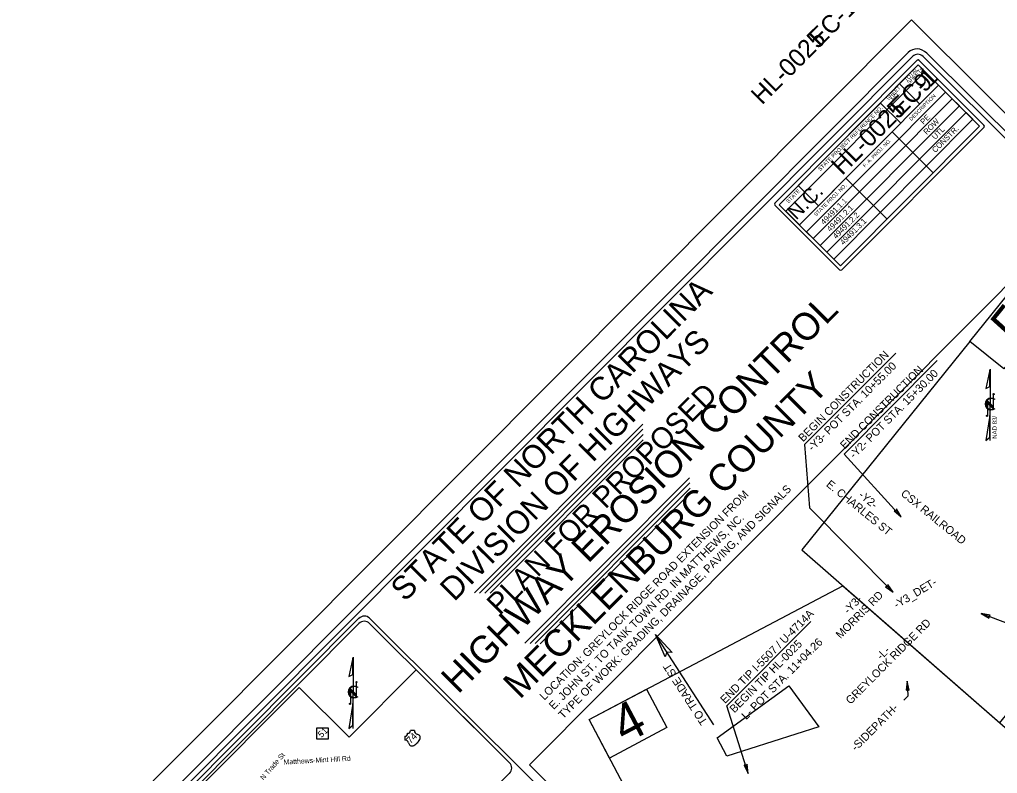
# Model space of a CAD drawing. Extents: x 1484932 to 1495672, y 495497 to 506262.
# Drawn here: x 1484932 to 1488841, y 498393 to 501407 of the extents above; entities that cross this region are included whole.
import ezdxf

# ---------------------------------------------------------------- set-up
doc = ezdxf.new("R2010")
doc.units = 0
for name, color, linetype in [('Default', 7, 'Continuous'), ('Old_Level_18', 7, 'Continuous'), ('Prop Dimension', 7, 'Continuous'), ('Prop DSN Text', 7, 'Continuous'), ('Prop DSN White Annotation Label', 7, 'Continuous'), ('Prop EOT', 7, 'Continuous'), ('Prop Horizontal Alignment Station Label', 7, 'Continuous'), ('Prop Terminator CELL', 7, 'Continuous'), ('Scratch_Level_4', 7, 'Continuous'), ('Sheet Data Field CELL', 7, 'Continuous'), ('Sheet North Arrow CELL', 7, 'Continuous'), ('Sheet Plot Border Outside CELL', 7, 'Continuous')]:
    doc.layers.add(name, color=color, linetype=linetype)

msp = doc.modelspace()

# ---------------------------------------------------------------- linework, layer by layer
at = {"layer": 'Default'}
for p, q in [((1486749.9, 499114.4), (1487422.5, 499789.9)), ((1486770.5, 499113.7), (1487423.4, 499769.3)), ((1486791.2, 499113), (1487425, 499748.6)), ((1486812.6, 499113.1), (1487423.8, 499726.9)), ((1486951.5, 498913.7), (1487610.2, 499575.2)), ((1486972.1, 498913), (1487611.1, 499554.6)), ((1486992.7, 498912.3), (1487611.9, 499534)), ((1487013.3, 498911.5), (1487612.7, 499513.4))]:
    msp.add_line(p, q, dxfattribs=at)
at = {"layer": 'Old_Level_18'}
for p, q in [((1490710.4, 499129.2), (1488558.1, 501272.7)), ((1485457.2, 498202.7), (1488502.1, 501260.3)), ((1488519.3, 501244), (1487950.3, 500672.7)), ((1488786.7, 500985.1), (1488527.5, 501243.8)), ((1488543.4, 501258.8), (1490253, 499556.3)), ((1488523.7, 501225.3), (1487967.5, 500666.8)), ((1487994.9, 500640.3), (1488550.8, 501198.4)), ((1488523.7, 501225.3), (1488449.3, 501149.8)), ((1488550.8, 501198.4), (1488523.7, 501225.3)), ((1488769.3, 500980.7), (1488523.7, 501225.3)), ((1488449.3, 501149.8), (1488529.9, 501068.7)), ((1488605.2, 501144.3), (1488049.3, 500586.1)), ((1488077.2, 500558.3), (1488633.1, 501116.5)), ((1488633.1, 501116.5), (1488605.2, 501144.3)), ((1488043.9, 500743.5), (1488372.9, 501073.1)), ((1488660, 501089.6), (1488103.8, 500531)), ((1488372.9, 501073.1), (1488453.9, 500992.3)), ((1488688.3, 501062.2), (1488660, 501089.6)), ((1488132.1, 500503.7), (1488688.3, 501062.2)), ((1488714.9, 501035.8), (1488158.6, 500477.2)), ((1488742.7, 501008), (1488714.9, 501035.8)), ((1488186.5, 500449.5), (1488742.7, 501008)), ((1488769.4, 500980.7), (1488213.1, 500422.2)), ((1488218.8, 500406.1), (1488787.1, 500976)), ((1488453.9, 500992.3), (1488419.9, 500958.1)), ((1488419.9, 500958.1), (1488584.1, 500794.7)), ((1488235, 500772.6), (1488125.3, 500662.4)), ((1488399.2, 500609), (1488235, 500772.6)), ((1488125.3, 500662.4), (1488043.9, 500743.5)), ((1487950.7, 500664.5), (1488209.7, 500406.5)), ((1487967.5, 500666.8), (1488213.1, 500422.2)), ((1488049.3, 500586.1), (1487994.9, 500640.3)), ((1488103.8, 500531), (1488077.2, 500558.3)), ((1488158.6, 500477.2), (1488132.1, 500503.7)), ((1488213.1, 500422.2), (1488186.5, 500449.5)), ((1485486.3, 498207.8), (1486288.2, 499013)), ((1486331.1, 499013.1), (1487008.3, 498338.6)), ((1485507.1, 498207.8), (1486288.3, 498992.3)), ((1486331.1, 498992.4), (1486890.1, 498435.7))]:
    msp.add_line(p, q, dxfattribs=at)
msp.add_lwpolyline([(1488483.8, 501275.3), (1485308.3, 498086.6)], dxfattribs=at)
for centre, start, end in [((1486309.7, 498991.6), 45.1186, 135.1186), ((1486309.7, 498970.9), 45.1186, 135.1186), ((1486868.7, 498414.2), 315.1186, 45.1186)]:
    msp.add_arc(centre, 30.3, start, end, dxfattribs=at)
for centre, major_axis, ratio, start_param, end_param in [((1488522.4, 501236.9), (-38.6, 38.4), 0.927398, 4.712389, 6.283185), ((1488523.6, 501238.9), (-21.4, 21.3), 0.927398, 4.712389, 6.283185), ((1488523.4, 501238.7), (-4.72, 4.7), 0.927398, 4.712389, 6.283185), ((1488523.5, 501239.8), (-4.29, 4.27), 0.927398, 4.712389, 6.283185), ((1488782.4, 500980.7), (-4.72, 4.7), 0.93232, 3.141593, 4.712389), ((1487954.6, 500668.5), (4.29, -4.27), 0.927398, 3.141593, 4.712389), ((1488214.1, 500410.8), (4.72, -4.7), 0.927398, 4.712389, 6.283185)]:
    msp.add_ellipse(centre, major_axis=major_axis, ratio=ratio, start_param=start_param, end_param=end_param, dxfattribs=at)
at = {"layer": 'Prop Dimension'}
for p, q in [((1488434, 500073.4), (1488069.9, 499707.7)), ((1488600.1, 500043.2), (1488228.3, 499669.8)), ((1488228.3, 499669.8), (1488455.9, 499419.4)), ((1488095, 498999.7), (1487759.2, 498662.6)), ((1489377.9, 498804), (1488775.9, 499031.9)), ((1488479.7, 498761.9), (1488482.6, 498702.3)), ((1488482.6, 498702.3), (1488466.7, 498686.4)), ((1487844.4, 498392.9), (1487759.2, 498662.6))]:
    msp.add_line(p, q, dxfattribs=at)
msp.add_lwpolyline([(1488069.9, 499707.7), (1488089.2, 499455.4), (1488423.2, 499117.7), (1488423.2, 499117.7)], dxfattribs=at)
at = {"layer": 'Prop DSN Text'}
msp.add_line((1487707.1, 498587.7), (1487474, 498947.7), dxfattribs=at)
at = {"layer": 'Prop DSN White Annotation Label'}
for points in [[(1489043.4, 500231.5), (1488865.6, 500011), (1488730.5, 500119.9), (1488908.3, 500340.4)], [(1488865.6, 500011), (1488730.5, 500119.9), (1488058.3, 499286.4), (1488849.5, 498594.9), (1489725.7, 499681.3), (1489043.4, 500231.5)], [(1487208.7, 498608.1), (1488222.1, 499143.2), (1488965.4, 498493.7), (1489025.4, 498380), (1487698.9, 497679.6)], [(1487208.7, 498608.1), (1487438.3, 498729.4), (1487519.4, 498575.9), (1487289.7, 498454.6)]]:
    msp.add_lwpolyline(points, close=True, dxfattribs=at)
at = {"layer": 'Prop EOT'}
for p, q in [((1486471.5, 498541.9), (1486471.5, 498526)), ((1486510.1, 498564.8), (1486494.3, 498564.6))]:
    msp.add_line(p, q, dxfattribs=at)
msp.add_lwpolyline([(1486120.2, 498530.3), (1486120.2, 498575.4), (1486165.2, 498575.5), (1486165.3, 498530.4)], close=True, dxfattribs=at)
for centre, radius, start, end in [((1486472.2, 498552.4), 10.6, 266.1975, 4.6682), ((1486483.7, 498563.9), 10.6, 265.569, 4.108), ((1486524.6, 498563.4), 14.5, 174.6433, 256.9786), ((1486519.8, 498535.5), 13.8, 344.5208, 83.5807), ((1486506, 498540.2), 28.4, 309.2442, 342.8049), ((1486472.8, 498511.5), 14.5, 13.2587, 95.1575), ((1486500.7, 498516.5), 13.8, 186.662, 285.7164), ((1486495.9, 498530.3), 28.4, 287.4324, 321.0045), ((1486521.5, 498510.3), 4.03, 81.6193, 148.6808), ((1486526, 498514.8), 4.03, 121.5524, 186.2514)]:
    msp.add_arc(centre, radius, start, end, dxfattribs=at)
at = {"layer": 'Prop Terminator CELL'}
for points in [[(1488427.6, 499442.4), (1488455.9, 499419.4), (1488436.9, 499450.9), (1488435.1, 499443.2)], [(1488393.5, 499138.9), (1488423.2, 499117.7), (1488402.3, 499147.9), (1488401, 499140.2)], [(1488811.7, 499025), (1488775.9, 499031.9), (1488807.5, 499013.1), (1488805.4, 499020.7)], [(1487511.7, 498859.5), (1487474, 498947.7), (1487539.8, 498877), (1487519.1, 498878)], [(1488487.6, 498726.2), (1488479.7, 498761.9), (1488475.1, 498725.4), (1488481.2, 498730.3)], [(1487827.6, 498425.4), (1487844.4, 498392.9), (1487839.6, 498429.3), (1487834.9, 498423)]]:
    msp.add_lwpolyline(points, close=True, dxfattribs=at)
at = {"layer": 'Scratch_Level_4'}
for p, q in [((1488508.1, 501403.2), (1488508.1, 501403.2)), ((1488541.2, 501351.2), (1488541.2, 501351.2)), ((1486517.2, 498807.1), (1486890.1, 498435.7)), ((1485525.4, 498210.9), (1486049, 498736.6)), ((1486890.2, 498393.4), (1486119.3, 497619.4))]:
    msp.add_line(p, q, dxfattribs=at)
for points in [[(1486969.7, 498427.7), (1489005, 500471.4), (1490008.1, 499472.4), (1487972.8, 497428.7)], [(1487759, 498462.3), (1487720.6, 498534.8), (1488006.4, 498743.3), (1488126.2, 498579.3)]]:
    msp.add_lwpolyline(points, close=True, dxfattribs=at)
msp.add_lwpolyline([(1486049, 498736.6), (1486248.8, 498537.6), (1486517.2, 498807.1)], dxfattribs=at)
msp.add_arc((1486869, 498414.5), 29.9, 315.1181, 45.1181, dxfattribs=at)
at = {"layer": 'Sheet North Arrow CELL'}
for p, q in [((1488812, 499724.1), (1488812.2, 500008.5)), ((1488822.9, 499909.5), (1488822.8, 499851.2)), ((1488822.8, 499860.3), (1488801.1, 499882)), ((1488801.1, 499882), (1488801.1, 499822.7)), ((1488822.8, 499858.1), (1488801.1, 499879.9)), ((1488801.1, 499879.9), (1488801.1, 499874.6)), ((1488822.8, 499852.8), (1488801.1, 499874.6)), ((1488801.1, 499874.6), (1488822.8, 499852.8)), ((1488822.8, 499851.2), (1488801.1, 499872.9)), ((1488830.9, 499887.8), (1488831.2, 499887.6)), ((1488822.8, 499852.8), (1488822.8, 499858.1)), ((1486265.7, 498572.7), (1486266, 498857.2)), ((1486276.6, 498708.9), (1486254.8, 498730.7)), ((1486254.8, 498730.7), (1486254.8, 498671.3)), ((1486276.6, 498706.8), (1486254.8, 498728.5)), ((1486254.8, 498728.5), (1486254.8, 498723.2)), ((1486276.6, 498758.2), (1486276.6, 498699.8)), ((1486284.6, 498736.4), (1486284.9, 498736.2)), ((1486276.6, 498701.4), (1486254.8, 498723.2)), ((1486254.8, 498723.2), (1486276.6, 498701.4)), ((1486276.6, 498699.8), (1486254.8, 498721.6)), ((1486276.6, 498701.4), (1486276.6, 498706.8))]:
    msp.add_line(p, q, dxfattribs=at)
for points in [[(1488810.3, 500006), (1488794, 499932.2), (1488810.2, 499940.4)], [(1488809.8, 499824.3), (1488793.6, 499724.1), (1488809.7, 499736.8)], [(1486264, 498854.7), (1486247.7, 498780.8), (1486263.9, 498789)], [(1486263.5, 498673), (1486247.3, 498572.7), (1486263.4, 498585.4)]]:
    msp.add_lwpolyline(points, close=True, dxfattribs=at)
for centre in [(1488825.2, 499909.5), (1488798.7, 499822.6), (1486278.9, 498758.1), (1486252.5, 498671.3)]:
    msp.add_circle(centre, 2.32, dxfattribs=at)
for centre, radius, start, end in [((1488815.1, 499869.9), 23.9, 47.7961, 312.3501), ((1488817.5, 499869.9), 22.4, 53.0511, 308.5848), ((1486268.9, 498718.5), 23.9, 47.7961, 312.3501), ((1486271.2, 498718.5), 22.4, 53.0511, 308.5848)]:
    msp.add_arc(centre, radius, start, end, dxfattribs=at)
at = {"layer": 'Sheet Plot Border Outside CELL'}
msp.add_lwpolyline([(1488496.6, 501405.6), (1484931.7, 497825.9), (1487270, 495497.3), (1490834.9, 499077)], close=True, dxfattribs=at)

# ---------------------------------------------------------------- texts
at = {"layer": 'Default'}
for s, height, rotation, p in [('EC-1', 71.07, 45.1182, (1488129.5, 501294.2)), ('HL-0025', 71.92, 45.1187, (1487899.5, 501062.7)), ('STATE OF NORTH CAROLINA', 92.714, 45.1186, (1486471.9, 499076.2)), ('HIGHWAY EROSION CONTROL', 109.027, 45.1186, (1486684.4, 498707.4)), ('DIVISION OF HIGHWAYS', 92.714, 45.1186, (1486669.1, 499077)), ('MECKLENBURG COUNTY', 107.571, 45.1182, (1486931.2, 498686)), ('PLAN FOR PROPOSED', 84.79, 45.1186, (1486851, 499022.2)), ('N Trade St', 20, 48.7859, (1485906.4, 498364.8)), ('Matthews-Mint Hill Rd', 20, 3.2578, (1485987.7, 498428.4))]:
    msp.add_text(s, height=height, rotation=rotation, dxfattribs=at).set_placement(p)
at = {"layer": 'Old_Level_18'}
for s, height, rotation, p in [('EC-1', 72.03, 45.1186, (1488453.1, 501015.7)), ('TOTAL', 15.45, 45.1186, (1488477, 501157)), ('SHEETS', 15.45, 45.1186, (1488488.5, 501147.2)), ('9', 71.9, 45.1187, (1488549.1, 501112.2)), ('SHEET', 15.45, 45.1186, (1488405.1, 501082.2)), ('NO.', 15.45, 45.1186, (1488424.9, 501080.7)), ('HL-0025', 72.03, 45.1186, (1488219.7, 500781.4)), ('DESCRIPTION', 14.828, 45.1186, (1488496.4, 501000.7)), ('STATE PROJECT REFERENCE NO.', 15.445, 45.1186, (1488132.6, 500800.1)), ('F. A. PROJ. NO.', 14.828, 45.1186, (1488310.7, 500814.3)), ('STATE', 15.45, 45.1186, (1488005.2, 500671.2)), ('N.C.', 59.8, 45.1186, (1488035.9, 500602.6)), ('STATE PROJ. NO.', 14.828, 45.1186, (1488115.9, 500618.7))]:
    msp.add_text(s, height=height, rotation=rotation, dxfattribs=at).set_placement(p)
at = {"layer": 'Prop DSN Text'}
for s, height, rotation, p in [('5', 150, 51.1156, (1488918.6, 500101.9)), ('BEGIN CONSTRUCTION', 32, 45.1191, (1488063.9, 499716.4)), ('-Y3- POT STA. 10+55.00', 32, 45.1191, (1488101.3, 499679.2)), ('END CONSTRUCTION', 32, 45.1191, (1488230.8, 499687)), ('-Y2- POT STA. 15+30.00', 32, 45.1191, (1488268.2, 499649.8)), ('LOCATION: GREYLOCK RIDGE ROAD EXTENSION FROM', 32, 45.1191, (1487029.7, 498683.3)), ('TYPE OF WORK: GRADING, DRAINAGE, PAVING, AND SIGNALS', 32, 45.1191, (1487104.5, 498608.8)), ('E. JOHN ST. TO TANK TOWN RD. IN MATTHEWS, NC.', 32, 45.1191, (1487067.1, 498646.1)), ('END TIP I-5507 / U-4714A', 32, 45.1191, (1487751.8, 498669.9)), ('BEGIN TIP HL-0025', 32, 45.1191, (1487789.3, 498632.7)), ('-L- POT STA. 11+04.26', 32, 45.1191, (1487826.7, 498595.4)), ('TO TRADE ST', 32, 122.9223, (1487682.9, 498599.7)), ('4', 150, 27.8403, (1487350.6, 498508.7))]:
    msp.add_text(s, height=height, rotation=rotation, dxfattribs=at).set_placement(p)
at = {"layer": 'Prop EOT'}
for s, height, p in [('51', 26.25, (1486139.3, 498533.9)), ('74', 27.5, (1486494.6, 498509.9))]:
    msp.add_text(s, height=height, rotation=45.1186, dxfattribs=at).set_placement(p)
at = {"layer": 'Prop Horizontal Alignment Station Label'}
for s, rotation, p in [('E. CHARLES ST', 320.9673, (1488153.4, 499543.8)), ('-Y2-', 320.9673, (1488283.1, 499500.5)), ('CSX RAILROAD', 320.9673, (1488451.5, 499506.6)), ('-Y3_DET-', 30.8554, (1488438.1, 499051.3)), ('MORRIS RD', 45.1191, (1488213.7, 498929.6)), ('-Y3-', 45.1191, (1488244.4, 499028.4)), ('GREYLOCK RIDGE RD', 45.1191, (1488253.2, 498667)), ('-L-', 45.1191, (1488376.4, 498845)), ('-SIDEPATH-', 45.1191, (1488274.8, 498480.3))]:
    msp.add_text(s, height=32, rotation=rotation, dxfattribs=at).set_placement(p)
at = {"layer": 'Sheet Data Field CELL'}
for s, p in [('PE', (1488545.7, 500985.7)), ('ROW', (1488558.2, 500945.1)), ('UTL', (1488591.7, 500925.3)), ('CONSTR.', (1488592.2, 500872.7)), ('49491.1.1', (1488147.2, 500585.2)), ('49491.2.1', (1488171.9, 500556.8)), ('49491.2.2', (1488196.2, 500528.1)), ('49491.3.1', (1488225, 500503.9))]:
    msp.add_text(s, height=22.5, rotation=45.1191, dxfattribs=at).set_placement(p)
at = {"layer": 'Sheet North Arrow CELL'}
msp.add_text('NAD 83/', height=17.5, rotation=89.9561, dxfattribs=at).set_placement((1488837.8, 499730.8))

doc.saveas('drawing.dxf')
